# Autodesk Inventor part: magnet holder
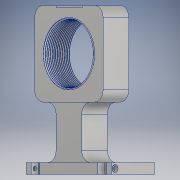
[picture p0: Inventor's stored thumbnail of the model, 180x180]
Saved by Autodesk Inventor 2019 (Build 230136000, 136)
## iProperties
Created: 2019-05
Part Number: magnet holder
Material: Aluminum 6061
Document SubType Name: Modeling
Designer: Chloe
Density: 2.7 g/cm^3
Appearance: Aluminum - Flat
Author: Chloe
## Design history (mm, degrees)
sketch "Sketch1"
  geometry: L1 (0, 0)-(-50, 0); L2 (-50, 0)-(-50, -100); L3 (-50, -100)-(0, -100); L4 (0, -100)-(0, 0); L5 (-42, -6)-(-50, -6); L6 (-50, -6)-(-50, -16); L7 (-50, -16)-(-42, -16); L8 (-42, -16)-(-42, -6); L9 (-42, -84)-(-50, -84); L10 (-50, -84)-(-50, -94); L11 (-50, -94)-(-42, -94); L12 (-42, -94)-(-42, -84); L13 (-10, -6.392)-(-32, -6.392); L14 (-10, -3.192)-(-32, -3.192); L15 (-32, -9.592)-(-10, -9.592); L16 (-10, -93.608)-(-32, -93.608); L17 (-10, -96.808)-(-32, -96.808); L18 (-32, -90.408)-(-10, -90.408); L19 (-10, -23.321)-(-10, -74.656); L20 (-6.8, -23.321)-(-6.8, -74.656); L21 (-13.2, -74.656)-(-13.2, -23.321); A1 r 3.2 centre (-10, -6.392) between (-10, -9.592) and (-10, -3.192); A2 r 3.2 centre (-32, -6.392) between (-32, -3.192) and (-32, -9.592); A3 r 3.2 centre (-10, -93.608) between (-10, -96.808) and (-10, -90.408); A4 r 3.2 centre (-32, -93.608) between (-32, -90.408) and (-32, -96.808); A5 r 3.2 centre (-10, -23.321) between (-6.8, -23.321) and (-13.2, -23.321); A6 r 3.2 centre (-10, -74.656) between (-13.2, -74.656) and (-6.8, -74.656); 3 further points
  constraints: 48 end point, 12 point on circle, 12 tangent, 9 parallel, 6 centre point, 5 horizontal, 3 midpoint, 3 perpendicular, 3 point on line, 1 vertical
  dimensions: "d0" = 50 distance of L3.end L2.end; "d1" = 100 distance of L2.end L1.end; "d2" = 8 distance between parallel lines of L8 L2; "d3" = 8 distance between parallel lines of L12 L2 (derived); "d4" = 10 distance between parallel lines of L5 L7; "d5" = 10 distance between parallel lines of L11 L9 (= d4); "d6" = 6 distance between parallel lines of L5 L1; "d7" = 6 distance between parallel lines of L3 L11 (= d6); "d10" = 6.4 distance between parallel lines of L18 L17 (= d11); "d11" = 6.4 distance between parallel lines of L15 L14; "d12" = 3.19173 distance between parallel lines of L14 L1; "d13" = 3.19173 distance between parallel lines of L17 L3 (= d12); "d16" = 87.21654 distance between parallel lines of L16 L13 (derived); "d17" = 10 distance from line of L4 point (-10, -48.988); "d18" = 6.4 distance between parallel lines of L20 L21 (= d11); "d22" = 10 distance from line of L4 L13.start (= d24 + d23); "d23" = 3.2 radius of A1 (derived); "d24" = 6.8 distance between parallel lines of L4 L20 (derived); "d25" = 10 distance from line of L8 L13.end (= d22); "d26" = 10 distance from line of L4 L16.start (= d22); "d27" = 10 distance from line of L12 L16.end (= d22)
extrude "Extrusion1" new body sketch "Sketch1" distance "d14" = 10; taper "d15" = 0 deg
sketch "Sketch2"
  geometry: L1 (49.992, -65)-(19.992, -65); L2 (19.992, -65)-(19.992, -35); L3 (19.992, -35)-(49.992, -35); L4 (49.992, -35)-(49.992, -65); L5 (0, -100)-(50, -100) reference; L6 (50, 0)-(0, 0) reference
  constraints: 8 end point, 2 parallel, 1 horizontal, 1 perpendicular
  dimensions: "d28" = 30 distance of L2.end L3.end; "d29" = 30 distance of L1.end L2.end; "d30" = 35 distance between parallel lines of L5 L1 (computed from d31); "d31" = 100 distance between parallel lines of L6 L5 (derived)
extrude "Extrusion2" join sketch "Sketch2" distance "d32" = 50; taper "d33" = 0 deg
sketch "Sketch3"
  geometry: L1 (50, -84)-(50, -16) reference; L2 (19.992, -90)-(50, -90); L3 (50, -90)-(50, -10); L4 (50, -10)-(19.992, -10); L5 (19.992, -10)-(19.992, -90); L6 (0, -100)-(50, -100) reference; 1 further point
  constraints: 8 end point, 2 parallel, 1 horizontal, 1 perpendicular, 1 point on line
  dimensions: "d34" = 80 distance between parallel lines of L4 L2; "d35" = 10 distance between parallel lines of L6 L2
extrude "Extrusion3" join sketch "Sketch3" distance "d36" = 80; taper "d37" = 0 deg
fillet "Fillet1" dims "d38" = 10
sketch "Sketch4"
  geometry: L1 (15, -10)-(15, -70) reference; L2 (-65, -10)-(-65, -70) reference; L3 (-50, 0)-(0, 0) reference; L4 (5, -80)-(-55, -80) reference; 2 further points
  dimensions: "d39" = 80 distance between parallel lines of L1 L2 (derived); "d40" = 80 distance between parallel lines of L3 L4 (derived); "d41" = 40 distance from line of L4 point (-25, -40) (= 0.5 x d40); "d42" = 40 distance from line of point (-25, -40) L2 (= 0.5 x d39)
hole "Hole1" sketch "Sketch4" at (-25, -40) diameter "d43" = 60; stored, may be unused: countersink angle "d47" = 82 deg, drill point angle "d49" = 118 deg; dims "d44" = 119.9896, "d45" = 9.525, "d46" = 6.35, "d48" = 129.286
sketch "Sketch5"
  geometry: L1 (49.992, -75)-(49.992, -25) reference; L2 (49.992, -64.574)-(22.992, -64.574); L3 (22.992, -64.574)-(22.992, -34.574); L4 (22.992, -34.574)-(49.992, -34.574); L5 (49.992, -34.574)-(49.992, -64.574); 1 further point
  constraints: 8 end point, 2 parallel, 1 horizontal, 1 perpendicular, 1 point on line
  dimensions: "d50" = 27 distance of L3.end L4.end; "d51" = 30 distance of L2.end L3.end
extrude "Extrusion4" cut sketch "Sketch5" distance "d52" = 2; taper "d53" = 0 deg
sketch "Sketch7"
  geometry: L1 (50, -10)-(0, -10) reference; L2 (0, 0)-(0, -10) reference; 2 further points
  dimensions: "d65" = 5 distance from line of point (4, -5) L1; "d66" = 4 distance from line of point (4, -5) L2
hole "Hole3" sketch "Sketch7" at (4, -5) diameter "d67" = 4.2; stored, may be unused: countersink angle "d71" = 82 deg, drill point angle "d73" = 118 deg; dims "d68" = 5, "d69" = 9.525, "d70" = 6.35, "d72" = 8.7884
sketch "Sketch8"
  geometry: C1 r 2.1 at (46, -5) reference; 2 further points
  constraints: 1 coincident
hole "Hole4" sketch "Sketch8" at (46, -5) diameter "d74" = 4.2; stored, may be unused: countersink angle "d78" = 82 deg, drill point angle "d80" = 0 deg; dims "d75" = 5, "d76" = 9.525, "d77" = 6.35, "d79" = 8.7884
sketch "Sketch9"
  geometry: C1 r 2.1 at (4, -5) reference; C2 r 3.5 at (4, -5); 1 further point
  constraints: 1 centre point, 1 coincident
  dimensions: "d81" = 7 diameter of C2
extrude "Extrusion5" cut sketch "Sketch9" distance "d82" = 4; taper "d83" = 0 deg
sketch "Sketch10"
  geometry: C1 r 2.1 at (46, -5) reference; C2 r 3.5 at (46, -5); 1 further point
  constraints: 1 centre point, 1 coincident
  dimensions: "d84" = 7 diameter of C2
extrude "Extrusion6" cut sketch "Sketch10" distance "d85" = 4; taper "d86" = 0 deg
thread "Thread1" dims "d93" = 25.4, "d94" = 0
sketch "Sketch14"
  geometry: L1 (30, 0)-(30, 30.008); L2 (30, 30.008)-(28.517, 30.008); L3 (28.517, 30.008)-(28.517, 0); L4 (28.517, 0)-(30, 0); L5 (0, -29.992)-(0, 40.008) reference
  constraints: 8 end point
revolve "Revolution2" sketch "Sketch14" stored, may be unused: angle "d122" = 0 deg
sketch "Sketch13"
  geometry: L1 (-1.167, -0.101)-(-1, -0.101); L2 (0.167, -1.382)-(0, -1.702); L3 (-2, -1.702)-(-2.167, -1.382); L4 (-0.833, -0.101)-(-1, 0.219); L5 (-1, 0.219)-(-1.167, -0.101); L6 (-2, -1.702)-(-1.833, -1.382); L7 (-0.833, -0.101)-(-0.167, -1.382); L8 (-2.167, -1.382)-(-1.833, -1.382); L9 (0.167, -1.382)-(-0.167, -1.382); L10 (-2, -1.702)-(-2, -1.382); L11 (0, -1.702)-(0, -1.382); L12 (-1, 0.219)-(-1, 0); L13 (-2, -1.483)-(0, -1.483); L14 (-0.167, -1.382)-(0, -1.702); L15 (-1.833, -1.382)-(-1.167, -0.101); L16 (0, 0)-(0, 0.018); L17 (0, 0.018)-(0, 0); L18 (0, 0)-(0.033, 0); L19 (-1, 0)-(-1, -0.101); L20 (-1, -0.101)-(-0.833, -0.101); A1 r 0.188 centre (-2, -1.295) between (-2.167, -1.382) and (-2, -1.483); A2 r 0.188 centre (-2, -1.295) between (-2, -1.483) and (-1.833, -1.382); A3 r 0.188 centre (0, -1.295) between (-0.167, -1.382) and (0, -1.483); A4 r 0.188 centre (0, -1.295) between (0, -1.483) and (0.167, -1.382); A5 r 0.188 centre (-1, -0.188) between (-1, 0) and (-1.167, -0.101); A6 r 0.188 centre (-1, -0.188) between (-0.833, -0.101) and (-1, 0)
  constraints: 40 end point, 12 point on circle, 10 parallel, 8 tangent, 6 centre point, 6 collinear, 2 midpoint, 2 point on line, 1 horizontal, 1 perpendicular, 3 other
  dimensions: "d113" = 55 deg angle of L7 L15 (= d120); "d114" = 0.32017 distance of L4.end L1.end (= 0.160083 x Sketch13_Pitch); "d115" = 0.32017 distance of L2.end L11.end (= 0.160083 x Sketch13_Pitch); "Sketch13_ThreadOffset" = 0 distance between parallel lines of L16 L11; "Sketch13_MajorRadius" = 1.48292 distance from line of L13 L16.start; "d118" = 2 distance from line of L2.end L10 (= Sketch13_Pitch); "Sketch13_MinorRadius" = 0 distance edge to line of A6 L18 (derived)
coil "Coil2" sketch "Sketch13" pitch "d123" = 2.002; turns "d125" = 1; dims "d124" = 34.00768, "d126" = 0, angle "d127" = 0 deg, angle "d128" = 0 deg, "d129" = 0, "d130" = 0
sketch "Sketch15"
  geometry: L1 (49.992, -64.574)-(22.992, -64.574); L2 (22.992, -34.574)-(49.992, -34.574); L3 (22.992, -64.574)-(22.992, -34.574); L4 (49.992, -34.574)-(49.992, -64.574); C1 r 1.5 at (29.992, -41.034); C2 r 1.5 at (29.992, -58.114); 3 further points
  constraints: 8 end point, 2 centre point, 1 coincident
  dimensions: "d131" = 20 distance from line of point (29.992, -41.034) L4; "d132" = 20 distance from line of L4 point (29.992, -58.114) (= d131); "d133" = 17.08 distance of point (29.992, -58.114) point (29.992, -41.034); "d134" = 6.46 distance from line of L2 point (29.992, -41.034) (= -0.5 x d133 + 0.5 x d135); "d135" = 30 distance between parallel lines of L1 L2 (derived); "d136" = 3 diameter of C1; "d137" = 3 diameter of C2
extrude "Extrusion7" cut sketch "Sketch15" distance "d138" = 5; taper "d139" = 0 deg
thread "Thread2" dims "d140" = 25.4, "d141" = 0
thread "Thread3" dims "d142" = 25.4, "d143" = 0
sketch "Sketch17"
  geometry: L1 (1.5, 0)-(1.5, 5); L2 (1.5, 5)-(1.129, 5); L3 (1.129, 5)-(1.129, 0); L4 (1.129, 0)-(1.5, 0); L5 (0, -161)-(0, 35) reference
  constraints: 8 end point
revolve "Revolution3" sketch "Sketch17" stored, may be unused: angle "d153" = 0 deg
sketch "Sketch16"
  geometry: L1 (-0.292, -0.025)-(-0.25, -0.025); L2 (0.042, -0.346)-(0, -0.426); L3 (-0.5, -0.426)-(-0.542, -0.346); L4 (-0.208, -0.025)-(-0.25, 0.055); L5 (-0.25, 0.055)-(-0.292, -0.025); L6 (-0.5, -0.426)-(-0.458, -0.346); L7 (-0.208, -0.025)-(-0.042, -0.346); L8 (-0.542, -0.346)-(-0.458, -0.346); L9 (0.042, -0.346)-(-0.042, -0.346); L10 (-0.5, -0.426)-(-0.5, -0.346); L11 (0, -0.426)-(0, -0.346); L12 (-0.25, 0.055)-(-0.25, 0); L13 (-0.5, -0.371)-(0, -0.371); L14 (-0.042, -0.346)-(0, -0.426); L15 (-0.458, -0.346)-(-0.292, -0.025); L16 (0, 0)-(0, 0.018); L17 (0, 0.018)-(0, 0); L18 (0, 0)-(0.033, 0); L19 (-0.25, 0)-(-0.25, -0.025); L20 (-0.25, -0.025)-(-0.208, -0.025); A1 r 0.047 centre (-0.5, -0.324) between (-0.542, -0.346) and (-0.5, -0.371); A2 r 0.047 centre (-0.5, -0.324) between (-0.5, -0.371) and (-0.458, -0.346); A3 r 0.047 centre (0, -0.324) between (-0.042, -0.346) and (0, -0.371); A4 r 0.047 centre (0, -0.324) between (0, -0.371) and (0.042, -0.346); A5 r 0.047 centre (-0.25, -0.047) between (-0.25, 0) and (-0.292, -0.025); A6 r 0.047 centre (-0.25, -0.047) between (-0.208, -0.025) and (-0.25, 0)
  constraints: 40 end point, 12 point on circle, 10 parallel, 8 tangent, 6 centre point, 6 collinear, 2 midpoint, 2 point on line, 1 horizontal, 1 perpendicular, 3 other
  dimensions: "d144" = 55 deg angle of L7 L15 (= d151); "d145" = 0.08004 distance of L4.end L1.end (= 0.160083 x Sketch16_Pitch); "d146" = 0.08004 distance of L2.end L11.end (= 0.160083 x Sketch16_Pitch); "Sketch16_ThreadOffset" = 0 distance between parallel lines of L16 L11; "Sketch16_MajorRadius" = 0.37073 distance from line of L13 L16.start; "d149" = 0.5 distance from line of L2.end L10 (= Sketch16_Pitch); "Sketch16_MinorRadius" = 0 distance edge to line of A6 L18 (derived)
coil "Coil3" sketch "Sketch16" pitch "d154" = 0.5005; turns "d156" = 1; dims "d155" = 6, "d157" = 0, angle "d158" = 0 deg, angle "d159" = 0 deg, "d160" = 0, "d161" = 0
sketch "Sketch19"
  geometry: L1 (1.5, 0)-(1.5, 5); L2 (1.5, 5)-(1.129, 5); L3 (1.129, 5)-(1.129, 0); L4 (1.129, 0)-(1.5, 0); L5 (0, -161)-(0, 35) reference
  constraints: 8 end point
revolve "Revolution4" sketch "Sketch19" stored, may be unused: angle "d171" = 0 deg
sketch "Sketch18"
  geometry: L1 (-0.292, -0.025)-(-0.25, -0.025); L2 (0.042, -0.346)-(0, -0.426); L3 (-0.5, -0.426)-(-0.542, -0.346); L4 (-0.208, -0.025)-(-0.25, 0.055); L5 (-0.25, 0.055)-(-0.292, -0.025); L6 (-0.5, -0.426)-(-0.458, -0.346); L7 (-0.208, -0.025)-(-0.042, -0.346); L8 (-0.542, -0.346)-(-0.458, -0.346); L9 (0.042, -0.346)-(-0.042, -0.346); L10 (-0.5, -0.426)-(-0.5, -0.346); L11 (0, -0.426)-(0, -0.346); L12 (-0.25, 0.055)-(-0.25, 0); L13 (-0.5, -0.371)-(0, -0.371); L14 (-0.042, -0.346)-(0, -0.426); L15 (-0.458, -0.346)-(-0.292, -0.025); L16 (0, 0)-(0, 0.018); L17 (0, 0.018)-(0, 0); L18 (0, 0)-(0.033, 0); L19 (-0.25, 0)-(-0.25, -0.025); L20 (-0.25, -0.025)-(-0.208, -0.025); A1 r 0.047 centre (-0.5, -0.324) between (-0.542, -0.346) and (-0.5, -0.371); A2 r 0.047 centre (-0.5, -0.324) between (-0.5, -0.371) and (-0.458, -0.346); A3 r 0.047 centre (0, -0.324) between (-0.042, -0.346) and (0, -0.371); A4 r 0.047 centre (0, -0.324) between (0, -0.371) and (0.042, -0.346); A5 r 0.047 centre (-0.25, -0.047) between (-0.25, 0) and (-0.292, -0.025); A6 r 0.047 centre (-0.25, -0.047) between (-0.208, -0.025) and (-0.25, 0)
  constraints: 40 end point, 12 point on circle, 10 parallel, 8 tangent, 6 centre point, 6 collinear, 2 midpoint, 2 point on line, 1 horizontal, 1 perpendicular, 3 other
  dimensions: "d162" = 55 deg angle of L7 L15 (= d169); "d163" = 0.08004 distance of L4.end L1.end (= 0.160083 x Sketch18_Pitch); "d164" = 0.08004 distance of L2.end L11.end (= 0.160083 x Sketch18_Pitch); "Sketch18_ThreadOffset" = 0 distance between parallel lines of L16 L11; "Sketch18_MajorRadius" = 0.37073 distance from line of L13 L16.start; "d167" = 0.5 distance from line of L2.end L10 (= Sketch18_Pitch); "Sketch18_MinorRadius" = 0 distance edge to line of A6 L18 (derived)
coil "Coil4" sketch "Sketch18" pitch "d172" = 0.5005; turns "d174" = 1; dims "d173" = 6, "d175" = 0, angle "d176" = 0 deg, angle "d177" = 0 deg, "d178" = 0, "d179" = 0
body "Solid1"
body "Solid3"
body "Solid4"
body "Solid5"
other parameters: "d102" = 55 deg [user parameter], "Sketch11_Pitch" = 2 [user parameter], "d120" = 55 deg [user parameter; used in 1 equation term], "Sketch13_Pitch" = 2 [user parameter; used in 3 equation terms], "d151" = 55 deg [user parameter; used in 1 equation term], "Sketch16_Pitch" = 0.5 [user parameter; used in 3 equation terms], "d169" = 55 deg [user parameter; used in 1 equation term], "Sketch18_Pitch" = 0.5 [user parameter; used in 3 equation terms]
